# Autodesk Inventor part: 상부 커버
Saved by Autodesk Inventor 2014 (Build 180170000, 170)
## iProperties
Created: 2026-08
Part Number: 상부 커버
Material: 일반
Document SubType Name: Modeling
Designer: dg
Density: 1 g/cm^3
Appearance: 기본값
Author: dg
Author: jhkim
Creation Date: 2026-07-31
Sending System: Autodesk Inventor 2027
Preprocessor: ST-DEVELOPER v20.1
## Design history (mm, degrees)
node "상부 커버1"
node "솔리드1"
node "기준1"
